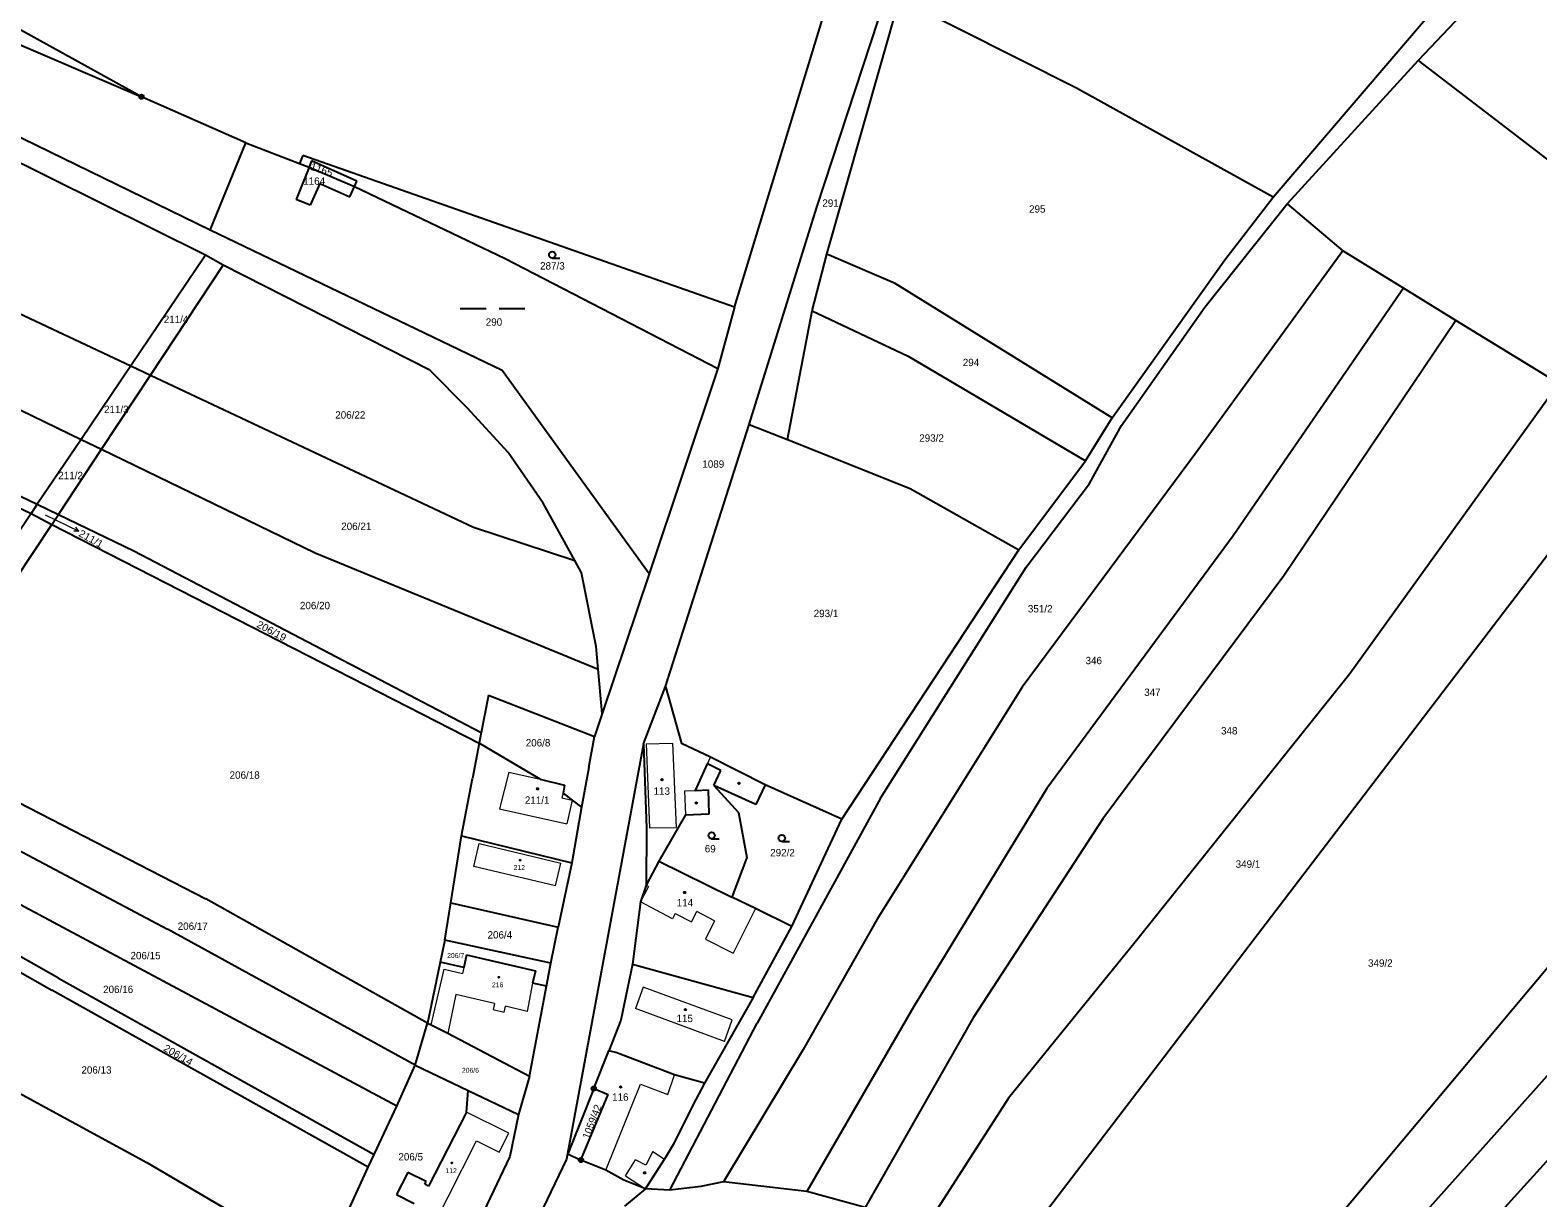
# Model space of a CAD drawing. Extents: x -694609 to -690140, y -1033292 to -1029794.
# Drawn here: x -692957.6 to -692609.2, y -1031085.6 to -1030815.9 of the extents above; entities that cross this region are included whole.
import ezdxf
from ezdxf.enums import TextEntityAlignment as Align

# ---------------------------------------------------------------- set-up
doc = ezdxf.new("R2010")
doc.units = 0
doc.header["$LTSCALE"] = 0.68
for name, color, linetype, lineweight in [('1', 7, 'Continuous', 25), ('3', 7, 'Continuous', 25), ('4', 7, 'Continuous', 13), ('5', 7, 'Continuous', 25), ('7', 7, 'Continuous', 13), ('8', 7, 'Continuous', 25)]:
    doc.layers.add(name, color=color, linetype=linetype, lineweight=lineweight)
doc.layers.add('2', color=7, linetype='Continuous')

msp = doc.modelspace()

# ---------------------------------------------------------------- linework, layer by layer
at = {"layer": '1'}
for p, q in [((-692775.8, -1030856.76), (-692734.63, -1030731.48)), ((-692931.9, -1030831.23), (-693003.31, -1030791.93)), ((-692606.75, -1030791.03), (-692636.81, -1030822.86)), ((-693018.11, -1030794.43), (-692931.9, -1030831.23)), ((-692670.33, -1030854.44), (-692622.76, -1030798.81)), ((-692794.84, -1030879.84), (-692772.17, -1030805.55)), ((-692917.1, -1030867.85), (-693037.79, -1030807.89)), ((-692773.49, -1030867.61), (-692756.72, -1030808.61)), ((-692715.77, -1030829.28), (-692756.72, -1030808.61)), ((-692916.05, -1030862.05), (-693020.03, -1030811.51)), ((-692636.81, -1030822.86), (-692667.14, -1030856)), ((-692636.81, -1030822.86), (-692496.66, -1030930.48)), ((-693069.12, -1030830.06), (-692934.37, -1030893.4)), ((-692907.77, -1030841.89), (-692931.9, -1030831.23)), ((-692670.33, -1030854.44), (-692715.77, -1030829.28)), ((-692916.05, -1030862.05), (-692907.77, -1030841.89)), ((-692907.77, -1030841.89), (-692895.38, -1030846.64)), ((-692894.62, -1030844.78), (-692895.38, -1030846.64)), ((-692794.84, -1030879.84), (-692894.62, -1030844.78)), ((-692893.16, -1030847.49), (-692896.15, -1030854.99)), ((-692895.38, -1030846.64), (-692893.16, -1030847.49)), ((-692892.62, -1030846.02), (-692893.16, -1030847.49)), ((-692893.16, -1030847.49), (-692882.67, -1030851.95)), ((-692882.11, -1030850.71), (-692892.62, -1030846.02)), ((-692890.67, -1030851.25), (-692892.92, -1030856.26)), ((-692890.67, -1030851.25), (-692883.73, -1030854.34)), ((-692883.73, -1030854.34), (-692882.67, -1030851.95)), ((-692882.67, -1030851.95), (-692882.11, -1030850.71)), ((-692882.67, -1030851.95), (-692847.88, -1030868.61)), ((-692892.92, -1030856.26), (-692896.15, -1030854.99)), ((-692686.14, -1030879.84), (-692667.14, -1030856)), ((-692681.49, -1030868.88), (-692670.33, -1030854.44)), ((-692667.14, -1030856), (-692654.26, -1030866.85)), ((-692791.46, -1030906.92), (-692775.8, -1030856.76)), ((-692848.52, -1030894.45), (-692916.05, -1030862.05)), ((-692917.1, -1030867.85), (-692934.37, -1030893.4)), ((-692929.81, -1030895.55), (-692912.99, -1030870.11)), ((-692912.99, -1030870.11), (-692917.1, -1030867.85)), ((-692865.29, -1030894.42), (-692912.99, -1030870.11)), ((-692847.88, -1030868.61), (-692798.68, -1030894.03)), ((-692776.93, -1030880.72), (-692773.49, -1030867.61)), ((-692757.74, -1030874.38), (-692773.49, -1030867.61)), ((-692707.56, -1030905.39), (-692681.49, -1030868.88)), ((-692654.26, -1030866.85), (-692688.27, -1030913.68)), ((-692640.22, -1030875.47), (-692654.26, -1030866.85)), ((-692707.56, -1030905.39), (-692757.74, -1030874.38)), ((-692640.22, -1030875.47), (-692679.61, -1030932.65)), ((-692628.1, -1030882.91), (-692640.22, -1030875.47)), ((-692794.84, -1030879.84), (-692798.68, -1030894.03)), ((-692705.41, -1030907.19), (-692686.14, -1030879.84)), ((-692782.63, -1030910.43), (-692776.93, -1030880.72)), ((-692776.93, -1030880.72), (-692754.74, -1030891.15)), ((-692628.1, -1030882.91), (-692667.86, -1030941.92)), ((-692604.33, -1030897.5), (-692628.1, -1030882.91)), ((-693041.81, -1030887.47), (-692957.41, -1030927.47)), ((-693037.51, -1030886.17), (-692955.99, -1030925.37)), ((-692934.37, -1030893.4), (-692945.85, -1030910.38)), ((-692934.37, -1030893.4), (-692929.81, -1030895.55)), ((-692856.65, -1030903.12), (-692865.29, -1030894.42)), ((-692814.6, -1030941.44), (-692848.52, -1030894.45)), ((-692798.68, -1030894.03), (-692814.6, -1030941.44)), ((-692754.74, -1030891.15), (-692713.72, -1030915.33)), ((-692971.97, -1030897.72), (-692945.85, -1030910.38)), ((-692941.13, -1030912.67), (-692929.81, -1030895.55)), ((-692929.81, -1030895.55), (-692855.2, -1030930.62)), ((-692604.33, -1030897.5), (-692652.6, -1030964.56)), ((-692847.19, -1030913.42), (-692856.65, -1030903.12)), ((-692810.76, -1030967.47), (-692791.46, -1030906.92)), ((-692791.46, -1030906.92), (-692782.63, -1030910.43)), ((-692713.72, -1030915.33), (-692707.56, -1030905.39)), ((-692712.81, -1030920.6), (-692705.41, -1030907.19)), ((-692945.85, -1030910.38), (-692955.99, -1030925.37)), ((-692945.85, -1030910.38), (-692941.13, -1030912.67)), ((-692782.63, -1030910.43), (-692754.25, -1030921.7)), ((-692730.32, -1031098.43), (-692585.59, -1030909.01)), ((-692951.09, -1030927.73), (-692941.13, -1030912.67)), ((-692941.13, -1030912.67), (-692891.77, -1030936.59)), ((-692839.05, -1030925.11), (-692847.19, -1030913.42)), ((-692729.13, -1030935.9), (-692713.72, -1030915.33)), ((-692688.27, -1030913.68), (-692709.73, -1030942.52)), ((-692754.25, -1030921.7), (-692729.13, -1030935.9)), ((-692727.45, -1030939.93), (-692712.81, -1030920.6)), ((-692955.99, -1030925.37), (-692957.41, -1030927.47)), ((-692955.99, -1030925.37), (-692951.09, -1030927.73)), ((-692831.78, -1030938.37), (-692839.05, -1030925.11)), ((-692661.64, -1031137.16), (-692467.96, -1030923.6)), ((-692957.41, -1030927.47), (-692991.38, -1030978.3)), ((-692957.41, -1030927.47), (-692952.63, -1030930.07)), ((-692952.63, -1030930.07), (-692951.09, -1030927.73)), ((-692951.09, -1030927.73), (-692933.65, -1030936.12)), ((-692986.42, -1030980.85), (-692952.63, -1030930.07)), ((-692952.63, -1030930.07), (-692853.82, -1030980.51)), ((-692855.2, -1030930.62), (-692831.78, -1030938.37)), ((-692679.61, -1030932.65), (-692722.64, -1030991.01)), ((-692933.65, -1030936.12), (-692853.36, -1030978.12)), ((-692770.02, -1030998.11), (-692729.13, -1030935.9)), ((-692497.1, -1030934.56), (-692671.89, -1031129.82)), ((-692891.77, -1030936.59), (-692826.36, -1030963.49)), ((-692830.23, -1030941.19), (-692831.78, -1030938.37)), ((-692826.83, -1030958.22), (-692830.23, -1030941.19)), ((-692814.6, -1030941.44), (-692825.45, -1030973.73)), ((-692761.1, -1030993.22), (-692727.45, -1030939.93)), ((-692709.73, -1030942.52), (-692728.36, -1030967.58)), ((-692667.86, -1030941.92), (-692709.68, -1030998.02)), ((-692826.36, -1030963.49), (-692826.83, -1030958.22)), ((-692825.45, -1030973.73), (-692826.36, -1030963.49)), ((-692815.84, -1030980.73), (-692810.76, -1030967.47)), ((-692810.76, -1030967.47), (-692807.06, -1030980.65)), ((-692728.36, -1030967.58), (-692761.86, -1031021.18)), ((-692652.6, -1030964.56), (-692702.21, -1031026.51)), ((-692851.7, -1030969.49), (-692853.36, -1030978.12)), ((-692851.7, -1030969.49), (-692827.21, -1030978.97)), ((-692825.45, -1030973.73), (-692827.21, -1030978.97)), ((-692853.36, -1030978.12), (-692853.82, -1030980.51)), ((-692986.42, -1030980.85), (-692917.02, -1031016.49)), ((-692853.82, -1030980.51), (-692855.4, -1030988.72)), ((-692839.79, -1030988.88), (-692853.82, -1030980.51)), ((-692815.84, -1030980.73), (-692833.67, -1031076.6)), ((-692828.53, -1030986.18), (-692827.21, -1030978.97)), ((-692815.84, -1030980.73), (-692815.21, -1031000.15)), ((-692800.39, -1030983.81), (-692807.06, -1030980.65)), ((-692787.74, -1030990.17), (-692800.39, -1030983.81)), ((-692828.53, -1030986.18), (-692830.17, -1030995.33)), ((-692803.84, -1030991.47), (-692801.06, -1030985.29)), ((-692798.02, -1030986.89), (-692801.06, -1030985.29)), ((-692799.6, -1030990.29), (-692798.02, -1030986.89)), ((-692569.75, -1030988.1), (-692683.18, -1031123.27)), ((-692991.63, -1030988.68), (-692925.86, -1031023.52)), ((-692857.98, -1031001.95), (-692855.4, -1030988.72)), ((-692839.79, -1030988.88), (-692834.11, -1030990.25)), ((-692834.11, -1030990.25), (-692834.46, -1030992.06)), ((-692803.84, -1030991.47), (-692800.89, -1030991.35)), ((-692800.67, -1030996.86), (-692800.89, -1030991.35)), ((-692789.95, -1030994.71), (-692799.6, -1030990.29)), ((-692799.6, -1030990.29), (-692793.91, -1030996.54)), ((-692722.64, -1030991.01), (-692753.38, -1031041.4)), ((-692830.17, -1030995.33), (-692832.45, -1031008.18)), ((-692761.1, -1030993.22), (-692789.57, -1031045.2)), ((-692872.91, -1031064.37), (-692997.76, -1030997.63)), ((-692806.14, -1030997.08), (-692812.36, -1031007.83)), ((-692806.14, -1030997.08), (-692800.67, -1030996.86)), ((-692793.91, -1030996.54), (-692791.96, -1031006.93)), ((-692781.57, -1031022.89), (-692770.02, -1030998.11)), ((-692709.68, -1030998.02), (-692739.71, -1031044)), ((-692860.41, -1031017.45), (-692857.98, -1031001.95)), ((-692857.98, -1031001.95), (-692832.45, -1031008.18)), ((-692815.21, -1031000.15), (-692815.23, -1031013.36)), ((-692951.06, -1031034.81), (-693002.85, -1031005.53)), ((-693004.63, -1031008.2), (-692952.63, -1031037.6)), ((-692832.45, -1031008.18), (-692835.57, -1031023.01)), ((-692812.36, -1031007.83), (-692815.23, -1031013.36)), ((-692812.36, -1031007.83), (-692795.49, -1031016.08)), ((-692791.96, -1031006.93), (-692795.49, -1031016.08)), ((-692815.23, -1031013.36), (-692816.6, -1031017.21)), ((-692790.03, -1031018.75), (-692795.49, -1031016.08)), ((-692865.8, -1031045.18), (-692917.02, -1031016.49)), ((-692861.81, -1031026.05), (-692860.41, -1031017.45)), ((-692860.41, -1031017.45), (-692835.57, -1031023.01)), ((-692816.6, -1031017.21), (-692818.39, -1031031.57)), ((-692781.57, -1031022.89), (-692790.03, -1031018.75)), ((-692837.33, -1031031.32), (-692835.57, -1031023.01)), ((-692790.53, -1031039.32), (-692781.57, -1031022.89)), ((-692761.86, -1031021.18), (-692779, -1031051.27)), ((-692868.66, -1031054.94), (-692925.86, -1031023.52)), ((-692861.81, -1031026.05), (-692862.86, -1031031.09)), ((-692837.33, -1031031.32), (-692861.81, -1031026.05)), ((-692702.21, -1031026.51), (-692731.5, -1031062.57)), ((-693018.79, -1031029.47), (-692930.66, -1031077.38)), ((-692856.76, -1031029.43), (-692857.39, -1031032.37)), ((-692856.76, -1031029.43), (-692840.86, -1031033.14)), ((-692862.86, -1031031.09), (-692865.8, -1031045.18)), ((-692857.39, -1031032.37), (-692862.86, -1031031.09)), ((-692840.86, -1031033.14), (-692841.5, -1031035.94)), ((-692838.32, -1031036.64), (-692837.33, -1031031.32)), ((-692818.39, -1031031.57), (-692821.13, -1031044.56)), ((-692818.39, -1031031.57), (-692790.53, -1031039.32)), ((-692951.06, -1031034.81), (-692878.15, -1031075.53)), ((-692842.21, -1031057.46), (-692838.32, -1031036.64)), ((-692838.32, -1031036.64), (-692841.5, -1031035.94)), ((-692879.49, -1031078.45), (-692952.63, -1031037.6)), ((-692790.53, -1031039.32), (-692801.81, -1031059.1)), ((-692753.38, -1031041.4), (-692778.16, -1031084.09)), ((-692739.71, -1031044), (-692764.66, -1031087.82)), ((-692868.66, -1031054.94), (-692865.8, -1031045.18)), ((-692865.8, -1031045.18), (-692864.96, -1031045.62)), ((-692864.96, -1031045.62), (-692861.11, -1031047.52)), ((-692861.11, -1031047.52), (-692842.21, -1031057.46)), ((-692821.13, -1031044.56), (-692823.92, -1031051.63)), ((-692809.81, -1031083.75), (-692789.57, -1031045.2)), ((-692779, -1031051.27), (-692797.36, -1031081.83)), ((-692827.36, -1031060.32), (-692823.92, -1031051.63)), ((-692822.24, -1031052.02), (-692823.92, -1031051.63)), ((-692808.69, -1031057.14), (-692822.24, -1031052.02)), ((-692872.91, -1031064.37), (-692868.66, -1031054.94)), ((-692868.66, -1031054.94), (-692856.41, -1031060.78)), ((-692842.21, -1031057.46), (-692844.79, -1031066.32)), ((-692801.81, -1031059.1), (-692808.69, -1031057.14)), ((-692856.77, -1031065.8), (-692856.41, -1031060.78)), ((-692856.41, -1031060.78), (-692844.79, -1031066.32)), ((-692830.33, -1031076.83), (-692824.07, -1031061.7)), ((-692827.36, -1031060.32), (-692824.07, -1031061.7)), ((-692801.81, -1031059.1), (-692804.45, -1031064.14)), ((-692878.15, -1031075.53), (-692872.91, -1031064.37)), ((-692804.45, -1031064.14), (-692808.92, -1031073.14)), ((-692731.5, -1031062.57), (-692750.62, -1031092.22)), ((-692856.77, -1031065.8), (-692865.54, -1031082.86)), ((-692844.79, -1031066.32), (-692846.75, -1031075.99)), ((-692879.49, -1031078.45), (-692878.15, -1031075.53)), ((-692808.92, -1031073.14), (-692811, -1031076.63)), ((-692930.66, -1031077.38), (-692890, -1031101.24)), ((-692890, -1031101.24), (-692879.49, -1031078.45)), ((-692846.75, -1031075.99), (-692858.01, -1031099.53)), ((-692833.67, -1031076.6), (-692857.71, -1031126.43)), ((-692824.61, -1031079.15), (-692830.33, -1031076.83)), ((-692820.41, -1031081.49), (-692824.61, -1031079.15)), ((-692815.42, -1031083.48), (-692811, -1031076.63)), ((-692870.38, -1031079.7), (-692872.93, -1031084.81)), ((-692866.13, -1031081.82), (-692870.38, -1031079.7)), ((-692866.42, -1031082.39), (-692866.13, -1031081.82)), ((-692865.54, -1031082.86), (-692866.42, -1031082.39)), ((-692815.42, -1031083.48), (-692820.41, -1031081.49)), ((-692797.36, -1031081.83), (-692802.66, -1031082.93)), ((-692778.16, -1031084.09), (-692797.36, -1031081.83)), ((-692872.93, -1031084.81), (-692868.88, -1031086.89)), ((-692815.42, -1031083.48), (-692820.24, -1031087.51)), ((-692809.81, -1031083.75), (-692815.42, -1031083.48)), ((-692802.66, -1031082.93), (-692809.81, -1031083.75)), ((-692764.66, -1031087.82), (-692778.16, -1031084.09))]:
    msp.add_line(p, q, dxfattribs=at)
for points in [[(-692834.46, -1030992.06), (-692832.37, -1030993.72), (-692830.17, -1030995.33)], [(-692770.02, -1030998.11), (-692787.74, -1030990.17), (-692789.95, -1030994.71)], [(-692827.36, -1031060.32), (-692833.33, -1031075.42), (-692830.33, -1031076.83)]]:
    msp.add_lwpolyline(points, dxfattribs=at)
at = {"layer": '3'}
for p, q in [((-692836.953, -1030868.51), (-692835.203, -1030868.51)), ((-692858.269, -1030880.13), (-692852.269, -1030880.13)), ((-692849.269, -1030880.13), (-692843.269, -1030880.13)), ((-692800.123, -1031002.63), (-692798.373, -1031002.63)), ((-692783.913, -1031003.23), (-692782.163, -1031003.23))]:
    msp.add_line(p, q, dxfattribs=at)
for centre in [(-692836.9529, -1030867.7598), (-692800.1229, -1031001.8798), (-692783.9129, -1031002.4798)]:
    msp.add_circle(centre, 0.75, dxfattribs=at)
at = {"layer": '4'}
for p, q in [((-692815.24, -1030980.71), (-692809.15, -1030980.54)), ((-692809.15, -1030980.54), (-692808.33, -1031000)), ((-692801.06, -1030985.29), (-692800.39, -1030983.81)), ((-692847.01, -1030987.26), (-692849.19, -1030995.69)), ((-692847.01, -1030987.26), (-692839.79, -1030988.88)), ((-692806.37, -1030991.57), (-692803.84, -1030991.47)), ((-692806.37, -1030991.57), (-692806.14, -1030997.08)), ((-692832.37, -1030993.72), (-692833.57, -1030999.14)), ((-692849.19, -1030995.69), (-692833.57, -1030999.14)), ((-692855.11, -1031009.03), (-692853.86, -1031003.75)), ((-692853.86, -1031003.75), (-692834.98, -1031008.24)), ((-692836.24, -1031013.52), (-692855.11, -1031009.03)), ((-692836.24, -1031013.52), (-692834.98, -1031008.24)), ((-692814.73, -1031013.62), (-692816.6, -1031017.21)), ((-692814.73, -1031013.62), (-692815.23, -1031013.36)), ((-692808.55, -1031019.9), (-692804.82, -1031021.84)), ((-692804.82, -1031021.84), (-692803.56, -1031019.42)), ((-692799.43, -1031021.56), (-692803.56, -1031019.42)), ((-692790.03, -1031018.75), (-692795.12, -1031029.02)), ((-692799.43, -1031021.56), (-692801.53, -1031025.85)), ((-692801.53, -1031025.85), (-692795.12, -1031029.02)), ((-692864.96, -1031045.62), (-692861.93, -1031032.73)), ((-692861.93, -1031032.73), (-692857.69, -1031033.73)), ((-692857.39, -1031032.37), (-692857.69, -1031033.73)), ((-692841.5, -1031035.94), (-692842.79, -1031042.49)), ((-692859.26, -1031038.61), (-692861.11, -1031047.52)), ((-692850.28, -1031040.69), (-692859.26, -1031038.61)), ((-692850.28, -1031040.69), (-692850.61, -1031042.06)), ((-692842.79, -1031042.49), (-692847.75, -1031041.3)), ((-692797.19, -1031049.42), (-692817.76, -1031041.85)), ((-692810.26, -1031061.66), (-692808.69, -1031057.14)), ((-692824.61, -1031079.15), (-692816.58, -1031059.27)), ((-692816.58, -1031059.27), (-692810.26, -1031061.66)), ((-692847.01, -1031070.6), (-692856.77, -1031065.8)), ((-692849.22, -1031074.99), (-692847.01, -1031070.6)), ((-692861.03, -1031085.32), (-692854.51, -1031072.38)), ((-692854.51, -1031072.38), (-692849.22, -1031074.99)), ((-692813.73, -1031074.88), (-692815.37, -1031078.04)), ((-692813.73, -1031074.88), (-692811, -1031076.63)), ((-692820.04, -1031080.48), (-692817.74, -1031076.81)), ((-692815.37, -1031078.04), (-692817.74, -1031076.81)), ((-692820.04, -1031080.48), (-692815.42, -1031083.48)), ((-692866.21, -1031095.51), (-692861.03, -1031085.32))]:
    msp.add_line(p, q, dxfattribs=at)
for points in [[(-692815.24, -1030980.71), (-692814.52, -1031000.13), (-692808.33, -1031000)], [(-692834.46, -1030992.06), (-692834.72, -1030993.2), (-692832.37, -1030993.72)], [(-692808.55, -1031019.9), (-692809.17, -1031021.08), (-692816.6, -1031017.21)], [(-692797.19, -1031049.42), (-692795.36, -1031044.42), (-692815.94, -1031036.9), (-692817.76, -1031041.85)], [(-692850.61, -1031042.06), (-692848.08, -1031042.67), (-692847.75, -1031041.3)]]:
    msp.add_lwpolyline(points, dxfattribs=at)
at = {"layer": '5'}
for centre, radius in [((-692840.3668, -1030991.0892), 0.175), ((-692811.5868, -1030988.9692), 0.175), ((-692793.7868, -1030989.8292), 0.175), ((-692803.6668, -1030994.3792), 0.175), ((-692844.3646, -1031007.5994), 0.1172), ((-692806.3768, -1031015.0392), 0.175), ((-692849.3246, -1031034.6194), 0.1172), ((-692806.1868, -1031042.0692), 0.175), ((-692821.1268, -1031059.9492), 0.175), ((-692860.1946, -1031077.4994), 0.1172), ((-692815.6268, -1031079.7892), 0.175)]:
    msp.add_circle(centre, radius, dxfattribs=at)
at = {"layer": '7'}
msp.add_line((-692946.413, -1030931.576), (-692947.093, -1030930.686), dxfattribs=at)
msp.add_lwpolyline([(-692954.17, -1030927.82), (-692949.11, -1030930.26), (-692946.413, -1030931.576), (-692947.532, -1030931.587)], dxfattribs=at)
at = {"layer": '8'}
for centre, radius in [((-692931.9, -1030831.2299), 0.5), ((-692931.9, -1030831.2299), 0.0303), ((-692827.36, -1031060.3199), 0.5), ((-692827.36, -1031060.3199), 0.0303), ((-692830.33, -1031076.8299), 0.5), ((-692830.33, -1031076.8299), 0.0303)]:
    msp.add_circle(centre, radius, dxfattribs=at)

# ---------------------------------------------------------------- texts
at = {"layer": '2', "width": 1.05}
for s, rotation, p in [('1165', 341, (-692890.5372, -1030848.9003)), ('211/1', 331, (-692943.9756, -1030934.0773)), ('206/19', 332, (-692902.2361, -1030955.3825)), ('206/14', 330, (-692923.836, -1031053.3019))]:
    msp.add_text(s, height=1.7, rotation=rotation, dxfattribs=at).set_placement(p, align=Align.CENTER)
at = {"layer": '2'}
for s, height, p in [('1164', 1.7, (-692891.99, -1030851.575)), ('291', 1.7, (-692772.639, -1030856.655)), ('295', 1.7, (-692724.869, -1030858.015)), ('287/3', 1.7, (-692836.94, -1030871.155)), ('211/4', 1.7, (-692923.91, -1030883.505)), ('290', 1.7, (-692850.439, -1030884.125)), ('294', 1.7, (-692740.189, -1030893.465)), ('211/3', 1.7, (-692937.72, -1030904.305)), ('206/22', 1.7, (-692883.64, -1030905.585)), ('293/2', 1.7, (-692749.3, -1030910.915)), ('1089', 1.7, (-692799.75, -1030916.935)), ('211/2', 1.7, (-692948.29, -1030919.575)), ('206/21', 1.7, (-692882.26, -1030931.305)), ('206/20', 1.7, (-692891.81, -1030949.605)), ('293/1', 1.7, (-692773.7, -1030951.435)), ('351/2', 1.7, (-692724.19, -1030950.355)), ('346', 1.7, (-692711.809, -1030962.305)), ('347', 1.7, (-692698.259, -1030969.635)), ('348', 1.7, (-692680.499, -1030978.535)), ('206/8', 1.7, (-692840.25, -1030981.305)), ('206/18', 1.7, (-692908.06, -1030988.765)), ('113', 1.7, (-692811.659, -1030992.465)), ('211/1', 1.7, (-692840.45, -1030994.555)), ('69', 1.7, (-692800.449, -1031005.775)), ('292/2', 1.7, (-692783.75, -1031006.675)), ('212', 1.14, (-692844.58, -1031009.845)), ('349/1', 1.7, (-692676.17, -1031009.325)), ('114', 1.7, (-692806.309, -1031018.225)), ('206/17', 1.7, (-692920.06, -1031023.665)), ('206/4', 1.7, (-692849.08, -1031025.665)), ('206/15', 1.7, (-692930.97, -1031030.455)), ('206/7', 1.14, (-692859.289, -1031030.165)), ('349/2', 1.7, (-692645.58, -1031032.185)), ('206/16', 1.7, (-692937.3, -1031038.255)), ('216', 1.14, (-692849.6, -1031036.925)), ('115', 1.7, (-692806.349, -1031044.965)), ('206/13', 1.7, (-692942.31, -1031056.865)), ('206/6', 1.14, (-692855.879, -1031056.675)), ('116', 1.7, (-692821.239, -1031063.125)), ('206/5', 1.7, (-692869.68, -1031076.925)), ('112', 1.14, (-692860.34, -1031079.845))]:
    msp.add_text(s, height=height, dxfattribs=at).set_placement(p, align=Align.CENTER)
msp.add_text('1059/42', height=1.7, rotation=69, dxfattribs=at).set_placement((-692828.473, -1031072.092))

doc.saveas('drawing.dxf')
